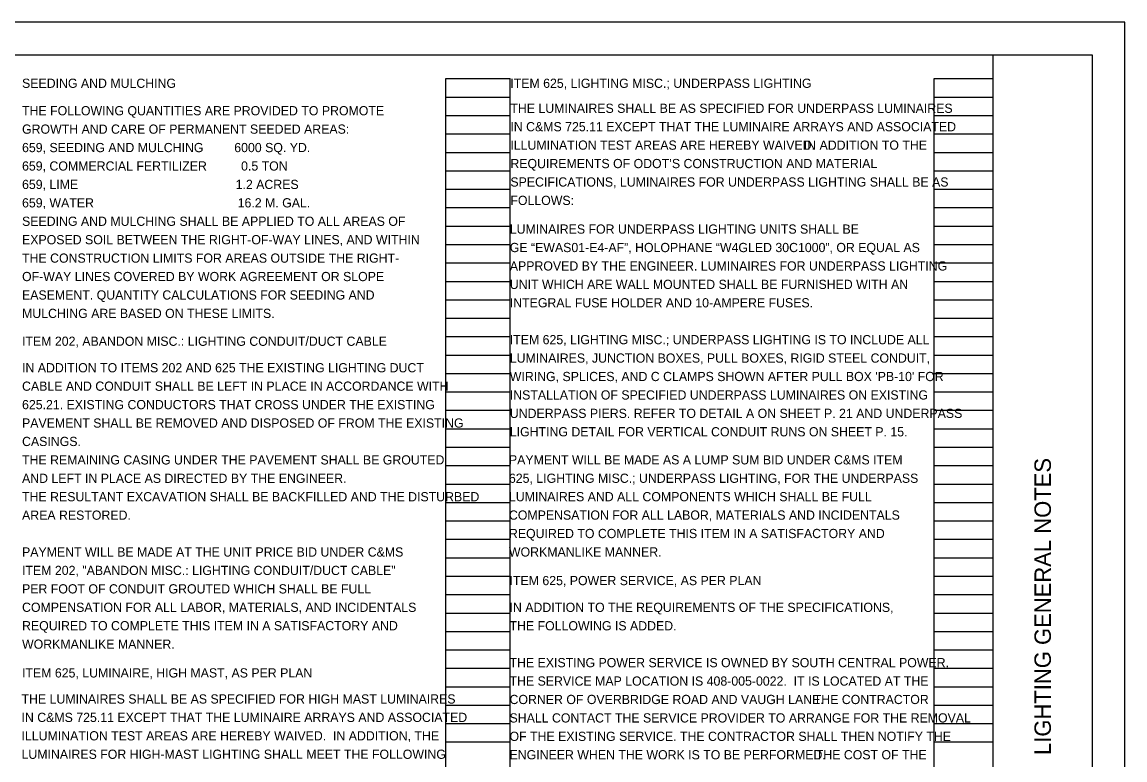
# Model space of a CAD drawing. Extents: x 0 to 34, y 0 to 22.
# Drawn here: x 17.24 to 34, y 10.79 to 22 of the extents above; entities that cross this region are included whole.
import ezdxf

# ---------------------------------------------------------------- set-up
doc = ezdxf.new("R2010")
doc.units = 0
for name, color, linetype in [('Default', 7, 'Continuous'), ('SH_Border', 7, 'Continuous'), ('SH_Cut_Line', 7, 'Continuous'), ('SH_Data', 7, 'Continuous'), ('SH_Text', 7, 'Continuous')]:
    doc.layers.add(name, color=color, linetype=linetype)

msp = doc.modelspace()

# ---------------------------------------------------------------- linework, layer by layer
at = {"layer": 'SH_Border'}
msp.add_line((32, 0.5), (32, 21.5), dxfattribs=at)
msp.add_lwpolyline([(1.5, 21.5), (33.5, 21.5), (33.5, 0.5), (1.5, 0.5)], close=True, dxfattribs=at)
at = {"layer": 'SH_Cut_Line'}
msp.add_lwpolyline([(0, 0), (34, 0), (34, 22), (0, 22)], close=True, dxfattribs=at)
at = {"layer": 'SH_Data'}
for p, q in [((23.68, 0.98), (23.68, 21.14)), ((23.68, 21.14), (24.66, 21.14)), ((24.66, 0.98), (24.66, 21.14)), ((31.1, 0.98), (31.1, 21.14)), ((31.1, 21.14), (32, 21.14)), ((32, 0.98), (32, 21.14)), ((23.68, 20.86), (24.66, 20.86)), ((31.1, 20.86), (32, 20.86)), ((23.68, 20.58), (24.66, 20.58)), ((31.1, 20.58), (32, 20.58)), ((23.68, 20.3), (24.66, 20.3)), ((31.1, 20.3), (32, 20.3)), ((23.68, 20.02), (24.66, 20.02)), ((31.1, 20.02), (32, 20.02)), ((23.68, 19.74), (24.66, 19.74)), ((31.1, 19.74), (32, 19.74)), ((23.68, 19.46), (24.66, 19.46)), ((31.1, 19.46), (32, 19.46)), ((23.68, 19.18), (24.66, 19.18)), ((31.1, 19.18), (32, 19.18)), ((23.68, 18.9), (24.66, 18.9)), ((31.1, 18.9), (32, 18.9)), ((23.68, 18.62), (24.66, 18.62)), ((31.1, 18.62), (32, 18.62)), ((23.68, 18.34), (24.66, 18.34)), ((31.1, 18.34), (32, 18.34)), ((23.68, 18.06), (24.66, 18.06)), ((31.1, 18.06), (32, 18.06)), ((23.68, 17.78), (24.66, 17.78)), ((31.1, 17.78), (32, 17.78)), ((23.68, 17.5), (24.66, 17.5)), ((31.1, 17.5), (32, 17.5)), ((23.68, 17.22), (24.66, 17.22)), ((31.1, 17.22), (32, 17.22)), ((23.68, 16.94), (24.66, 16.94)), ((31.1, 16.94), (32, 16.94)), ((23.68, 16.66), (24.66, 16.66)), ((31.1, 16.66), (32, 16.66)), ((23.68, 16.38), (24.66, 16.38)), ((31.1, 16.38), (32, 16.38)), ((23.68, 16.1), (24.66, 16.1)), ((31.1, 16.1), (32, 16.1)), ((23.68, 15.82), (24.66, 15.82)), ((31.1, 15.82), (32, 15.82)), ((23.68, 15.54), (24.66, 15.54)), ((31.1, 15.54), (32, 15.54)), ((23.68, 15.26), (24.66, 15.26)), ((31.1, 15.26), (32, 15.26)), ((23.68, 14.98), (24.66, 14.98)), ((31.1, 14.98), (32, 14.98)), ((23.68, 14.7), (24.66, 14.7)), ((31.1, 14.7), (32, 14.7)), ((23.68, 14.42), (24.66, 14.42)), ((31.1, 14.42), (32, 14.42)), ((23.68, 14.14), (24.66, 14.14)), ((31.1, 14.14), (32, 14.14)), ((23.68, 13.86), (24.66, 13.86)), ((31.1, 13.86), (32, 13.86)), ((23.68, 13.58), (24.66, 13.58)), ((31.1, 13.58), (32, 13.58)), ((23.68, 13.3), (24.66, 13.3)), ((31.1, 13.3), (32, 13.3)), ((23.68, 13.02), (24.66, 13.02)), ((31.1, 13.02), (32, 13.02)), ((23.68, 12.74), (24.66, 12.74)), ((31.1, 12.74), (32, 12.74)), ((23.68, 12.46), (24.66, 12.46)), ((31.1, 12.46), (32, 12.46)), ((23.68, 12.18), (24.66, 12.18)), ((31.1, 12.18), (32, 12.18)), ((23.68, 11.9), (24.66, 11.9)), ((31.1, 11.9), (32, 11.9)), ((23.68, 11.62), (24.66, 11.62)), ((31.1, 11.62), (32, 11.62)), ((23.68, 11.34), (24.66, 11.34)), ((31.1, 11.34), (32, 11.34)), ((23.68, 11.06), (24.66, 11.06)), ((31.1, 11.06), (32, 11.06))]:
    msp.add_line(p, q, dxfattribs=at)

# ---------------------------------------------------------------- texts
at = {"layer": 'Default'}
for s, p in [('ITEM 625, LIGHTING MISC.; UNDERPASS LIGHTING', (24.66, 21)), ('THE LUMINAIRES SHALL BE AS SPECIFIED FOR UNDERPASS LUMINAIRES ', (24.661, 20.62)), ('IN C&MS 725.11 EXCEPT THAT THE LUMINAIRE ARRAYS AND ASSOCIATED ', (24.661, 20.34)), ('ILLUMINATION TEST AREAS ARE HEREBY WAIVED. ', (24.661, 20.06)), ('IN ADDITION TO THE ', (29.12, 20.06)), ('REQUIREMENTS OF ODOT’S CONSTRUCTION AND MATERIAL ', (24.661, 19.78)), ('SPECIFICATIONS, LUMINAIRES FOR UNDERPASS LIGHTING SHALL BE AS ', (24.661, 19.5)), ('FOLLOWS: ', (24.661, 19.22)), ('LUMINAIRES FOR UNDERPASS LIGHTING UNITS SHALL BE ', (24.652, 18.784)), ('GE “EWAS01-E4-AF”, HOLOPHANE “W4GLED 30C1000”, OR EQUAL AS ', (24.652, 18.504)), ('APPROVED BY THE ENGINEER. LUMINAIRES FOR UNDERPASS LIGHTING ', (24.652, 18.224)), ('UNIT WHICH ARE WALL MOUNTED SHALL BE FURNISHED WITH AN ', (24.652, 17.944)), ('INTEGRAL FUSE HOLDER AND 10-AMPERE FUSES. ', (24.652, 17.664)), ('ITEM 625, LIGHTING MISC.; UNDERPASS LIGHTING IS TO INCLUDE ALL ', (24.652, 17.104)), ('LUMINAIRES, JUNCTION BOXES, PULL BOXES, RIGID STEEL CONDUIT, ', (24.652, 16.824)), ("WIRING, SPLICES, AND C CLAMPS SHOWN AFTER PULL BOX 'PB-10' FOR ", (24.652, 16.544)), ('INSTALLATION OF SPECIFIED UNDERPASS LUMINAIRES ON EXISTING ', (24.652, 16.264)), ('UNDERPASS PIERS. REFER TO DETAIL A ON SHEET P. 21 AND UNDERPASS ', (24.652, 15.984)), ('LIGHTING DETAIL FOR VERTICAL CONDUIT RUNS ON SHEET P. 15.', (24.652, 15.704)), ('PAYMENT WILL BE MADE AS A LUMP SUM BID UNDER C&MS ITEM ', (24.639, 15.278)), ('625, LIGHTING MISC.; UNDERPASS LIGHTING, FOR THE UNDERPASS ', (24.639, 14.998)), ('LUMINAIRES AND ALL COMPONENTS WHICH SHALL BE FULL ', (24.639, 14.718)), ('COMPENSATION FOR ALL LABOR, MATERIALS AND INCIDENTALS ', (24.639, 14.438)), ('REQUIRED TO COMPLETE THIS ITEM IN A SATISFACTORY AND ', (24.639, 14.158)), ('WORKMANLIKE MANNER.', (24.639, 13.878)), ('THE LUMINAIRES SHALL BE AS SPECIFIED FOR HIGH MAST LUMINAIRES ', (17.232, 11.644)), ('IN C&MS 725.11 EXCEPT THAT THE LUMINAIRE ARRAYS AND ASSOCIATED ', (17.232, 11.364)), ('ILLUMINATION TEST AREAS ARE HEREBY WAIVED.  IN ADDITION, THE ', (17.232, 11.084)), ('LUMINAIRES FOR HIGH-MAST LIGHTING SHALL MEET THE FOLLOWING ', (17.232, 10.804))]:
    msp.add_text(s, height=0.14, dxfattribs=at).set_placement(p)
at = {"layer": 'SH_Data'}
msp.add_text('LIGHTING GENERAL NOTES', height=0.25, rotation=90, dxfattribs=at).set_placement((32.875, 10.862))
at = {"layer": 'SH_Text'}
for s, p in [('SEEDING AND MULCHING', (17.24, 21)), ('THE FOLLOWING QUANTITIES ARE PROVIDED TO PROMOTE', (17.24, 20.583)), ('GROWTH AND CARE OF PERMANENT SEEDED AREAS:', (17.24, 20.303)), ('659, SEEDING AND MULCHING         6000 SQ. YD.', (17.24, 20.023)), ('659, COMMERCIAL FERTILIZER          0.5 TON', (17.24, 19.743)), ('659, LIME                                              1.2 ACRES', (17.24, 19.463)), ('659, WATER                                          16.2 M. GAL.', (17.24, 19.183)), ('SEEDING AND MULCHING SHALL BE APPLIED TO ALL AREAS OF', (17.24, 18.903)), ('EXPOSED SOIL BETWEEN THE RIGHT-OF-WAY LINES, AND WITHIN', (17.24, 18.623)), ('THE CONSTRUCTION LIMITS FOR AREAS OUTSIDE THE RIGHT-', (17.24, 18.343)), ('OF-WAY LINES COVERED BY WORK AGREEMENT OR SLOPE', (17.24, 18.063)), ('EASEMENT. QUANTITY CALCULATIONS FOR SEEDING AND', (17.24, 17.783)), ('MULCHING ARE BASED ON THESE LIMITS.', (17.24, 17.503)), ('ITEM 202, ABANDON MISC.: LIGHTING CONDUIT/DUCT CABLE', (17.24, 17.08)), ('IN ADDITION TO ITEMS 202 AND 625 THE EXISTING LIGHTING DUCT ', (17.24, 16.677)), ('CABLE AND CONDUIT SHALL BE LEFT IN PLACE IN ACCORDANCE WITH ', (17.24, 16.397)), ('625.21. EXISTING CONDUCTORS THAT CROSS UNDER THE EXISTING ', (17.24, 16.117)), ('PAVEMENT SHALL BE REMOVED AND DISPOSED OF FROM THE EXISTING ', (17.24, 15.837)), ('CASINGS. ', (17.24, 15.557)), ('THE REMAINING CASING UNDER THE PAVEMENT SHALL BE GROUTED ', (17.24, 15.277)), ('AND LEFT IN PLACE AS DIRECTED BY THE ENGINEER.', (17.24, 14.997)), ('THE RESULTANT EXCAVATION SHALL BE BACKFILLED AND THE DISTURBED', (17.24, 14.717)), ('AREA RESTORED.', (17.24, 14.437)), ('PAYMENT WILL BE MADE AT THE UNIT PRICE BID UNDER C&MS', (17.24, 13.877)), ('ITEM 202, "ABANDON MISC.: LIGHTING CONDUIT/DUCT CABLE" ', (17.24, 13.597)), ('ITEM 625, POWER SERVICE, AS PER PLAN', (24.648, 13.443)), ('PER FOOT OF CONDUIT GROUTED WHICH SHALL BE FULL ', (17.24, 13.317)), ('COMPENSATION FOR ALL LABOR, MATERIALS, AND INCIDENTALS ', (17.24, 13.037)), ('IN ADDITION TO THE REQUIREMENTS OF THE SPECIFICATIONS,', (24.648, 13.036)), ('REQUIRED TO COMPLETE THIS ITEM IN A SATISFACTORY AND ', (17.24, 12.757)), ('THE FOLLOWING IS ADDED.', (24.648, 12.756)), ('WORKMANLIKE MANNER.', (17.24, 12.477)), ('THE EXISTING POWER SERVICE IS OWNED BY SOUTH CENTRAL POWER.  ', (24.648, 12.196)), ('ITEM 625, LUMINAIRE, HIGH MAST, AS PER PLAN', (17.24, 12.04)), ('THE SERVICE MAP LOCATION IS 408-005-0022.  IT IS LOCATED AT THE ', (24.648, 11.916)), ('CORNER OF OVERBRIDGE ROAD AND VAUGH LANE. ', (24.648, 11.636)), ('THE CONTRACTOR ', (29.271, 11.636)), ('SHALL CONTACT THE SERVICE PROVIDER TO ARRANGE FOR THE REMOVAL ', (24.648, 11.356)), ('OF THE EXISTING SERVICE. THE CONTRACTOR SHALL THEN NOTIFY THE ', (24.648, 11.076)), ('ENGINEER WHEN THE WORK IS TO BE PERFORMED.', (24.648, 10.796)), (' THE COST OF THE ', (29.25, 10.796))]:
    msp.add_text(s, height=0.14, dxfattribs=at).set_placement(p)

doc.saveas('drawing.dxf')
